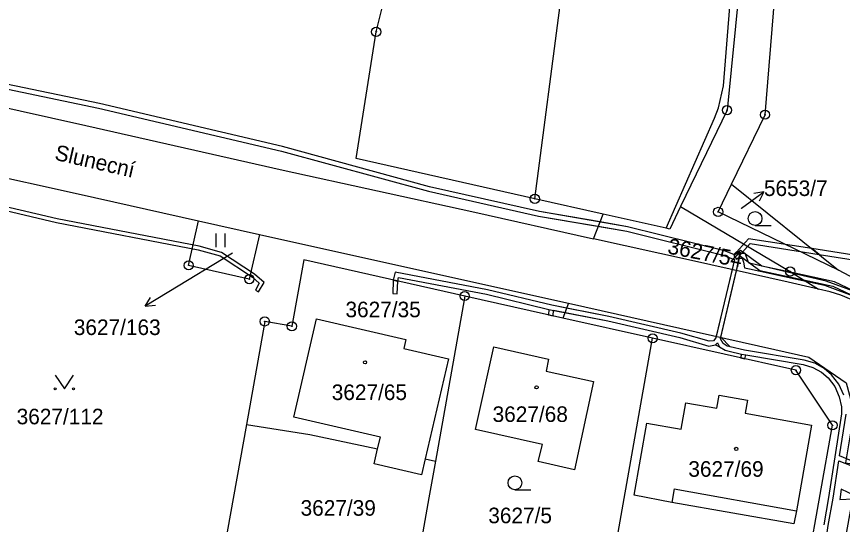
# Model space of a CAD drawing. Extents: x -644096 to -634268, y -1141430 to -1133463.
# Drawn here: x -640663.3 to -640573.2, y -1137723.5 to -1137668.1 of the extents above; entities that cross this region are included whole.
import ezdxf

# ---------------------------------------------------------------- set-up
doc = ezdxf.new("R2010")
doc.units = 0
for name, color, linetype in [('_CIVIL_CONSTRUCTION', 7, 'Continuous'), ('B_Hranice _3D', 7, 'Continuous'), ('M_Svah_Nasyp', 7, 'Continuous'), ('M_Svah_Zarez', 7, 'Continuous'), ('svrsek_osa_sjezdy', 7, 'Continuous'), ('svrsek_osa_VRT', 7, 'Continuous'), ('svrsek_popisy_VRT', 7, 'Continuous'), ('terminal_VRT', 7, 'Continuous')]:
    doc.layers.add(name, color=color, linetype=linetype)

msp = doc.modelspace()

# ---------------------------------------------------------------- linework, layer by layer
at = {"layer": '_CIVIL_CONSTRUCTION'}
for centre, radius in [((-640624.08, -1137669.79), 0.5), ((-640624.08, -1137669.79), 0.0303), ((-640585.78, -1137678.34), 0.5), ((-640585.78, -1137678.34), 0.0303), ((-640581.63, -1137678.84), 0.5), ((-640581.63, -1137678.84), 0.0303), ((-640606.76, -1137688.01), 0.5), ((-640606.76, -1137688.01), 0.0303), ((-640586.75, -1137689.44), 0.5), ((-640586.75, -1137689.44), 0.0303), ((-640644.55, -1137695.27), 0.5), ((-640644.55, -1137695.27), 0.0303), ((-640578.89, -1137695.94), 0.5), ((-640637.93, -1137696.78), 0.5), ((-640578.89, -1137695.94), 0.0303), ((-640637.93, -1137696.78), 0.0303), ((-640614.41, -1137698.62), 0.5), ((-640614.41, -1137698.62), 0.0303), ((-640636.24, -1137701.39), 0.5), ((-640636.24, -1137701.39), 0.0303), ((-640633.28, -1137701.92), 0.5), ((-640633.28, -1137701.92), 0.0303), ((-640593.9, -1137703.23), 0.5), ((-640593.9, -1137703.23), 0.0303), ((-640578.26, -1137706.71), 0.5), ((-640578.26, -1137706.71), 0.0303), ((-640574.26, -1137712.72), 0.5), ((-640574.26, -1137712.72), 0.0303)]:
    msp.add_circle(centre, radius, dxfattribs=at)
at = {"layer": 'B_Hranice _3D'}
for points in [[(-640549.77, -1137578.81), (-640550.43, -1137582.83), (-640551.07, -1137598.09), (-640551.86, -1137613.51), (-640556.82, -1137647.62), (-640558.57, -1137666.41), (-640560, -1137686.48), (-640560.91, -1137694.7), (-640563.67, -1137695.47), (-640576.51, -1137693.45), (-640575.72, -1137694.09), (-640563.65, -1137695.99), (-640560.45, -1137695.1), (-640559.5, -1137686.52), (-640558.07, -1137666.45), (-640556.32, -1137647.68), (-640551.36, -1137613.55), (-640550.57, -1137598.11), (-640549.93, -1137582.89), (-640549.27, -1137578.87), (-640548.65, -1137573.37), (-640549.08, -1137572.82)], [(-640583.45, -1137692.36), (-640584.76, -1137693.83), (-640584.38, -1137694.17), (-640583.25, -1137692.9), (-640575.72, -1137694.09), (-640576.51, -1137693.45)], [(-640562.15, -1137701.9), (-640563.49, -1137703.46), (-640564.2, -1137703.86), (-640565.14, -1137703.38), (-640567.68, -1137700.83), (-640570.04, -1137698.97), (-640574.05, -1137697.06), (-640578.7, -1137696.06), (-640581.98, -1137695.35), (-640584.32, -1137693.66), (-640585.05, -1137694.18), (-640584.76, -1137694.59), (-640584.32, -1137694.28), (-640582.19, -1137695.82), (-640577.42, -1137696.85), (-640574.21, -1137697.54), (-640570.3, -1137699.39), (-640568.02, -1137701.21), (-640565.44, -1137703.78), (-640564.18, -1137704.42), (-640563.15, -1137703.84), (-640561.7, -1137702.13)], [(-640538.26, -1137717), (-640539.71, -1137717.66), (-640559.3, -1137716.67), (-640560.67, -1137716.88), (-640562.49, -1137718.19), (-640563.8, -1137720.76), (-640564.48, -1137721.49), (-640565.79, -1137721.76), (-640571.78, -1137720.4), (-640573.31, -1137719.7), (-640573.48, -1137720.81), (-640572.04, -1137720.75), (-640565.8, -1137722.19), (-640564.28, -1137721.85), (-640563.47, -1137721), (-640562.18, -1137718.46), (-640560.51, -1137717.26), (-640559.28, -1137717.07), (-640541.12, -1137717.99), (-640538.13, -1137718.42), (-640537.86, -1137718.44), (-640537.1, -1137717.5)]]:
    msp.add_lwpolyline(points, close=True, dxfattribs=at)
for points in [[(-640570.99, -1137698.44), (-640574.97, -1137696.98), (-640578.55, -1137696.15), (-640583.18, -1137695.08), (-640583.41, -1137695.03), (-640583.8, -1137693.98), (-640584.54, -1137693.98), (-640585.02, -1137694.09), (-640586.04, -1137693.67), (-640596.63, -1137691.06), (-640599.64, -1137690.54), (-640606.25, -1137689.4), (-640618.24, -1137686.69), (-640634.31, -1137682.32), (-640654.28, -1137677.63), (-640676.38, -1137673.04)], [(-640585.44, -1137704.15), (-640585.77, -1137704.07), (-640586.21, -1137703.79), (-640586.49, -1137703.27), (-640584.32, -1137694.03), (-640584.78, -1137693.84), (-640585.02, -1137694.09), (-640586.04, -1137693.67), (-640596.63, -1137691.06), (-640606.25, -1137689.4), (-640618.24, -1137686.69), (-640634.31, -1137682.32), (-640654.28, -1137677.63), (-640676.38, -1137673.04)], [(-640676.48, -1137673.52), (-640654.38, -1137678.11), (-640634.43, -1137682.8), (-640618.36, -1137687.17), (-640606.35, -1137689.9), (-640599.83, -1137691.01), (-640596.73, -1137691.54), (-640586.2, -1137694.15), (-640585.18, -1137694.57), (-640584.97, -1137694.62), (-640585.23, -1137695.74), (-640586.95, -1137703.01), (-640586.99, -1137703.19), (-640587.27, -1137703.49), (-640587.74, -1137703.55), (-640590.81, -1137702.68), (-640598.68, -1137700.84), (-640603.29, -1137699.95), (-640604.92, -1137699.63), (-640611.92, -1137697.95), (-640622.01, -1137696.03), (-640622.21, -1137696.87), (-640621.72, -1137696.98), (-640621.63, -1137696.61), (-640612.02, -1137698.43), (-640605.23, -1137700.07), (-640598.78, -1137701.32), (-640590.93, -1137703.16), (-640587.78, -1137704.07), (-640587.03, -1137703.95), (-640586.59, -1137704.15), (-640585.97, -1137704.53)], [(-640676.48, -1137673.52), (-640654.38, -1137678.11), (-640634.43, -1137682.8), (-640618.36, -1137687.17), (-640606.35, -1137689.9), (-640596.73, -1137691.54), (-640586.2, -1137694.15), (-640585.18, -1137694.57), (-640584.97, -1137694.62), (-640586.99, -1137703.19), (-640587.27, -1137703.49), (-640587.74, -1137703.55), (-640590.81, -1137702.68), (-640598.68, -1137700.84), (-640604.92, -1137699.63), (-640611.92, -1137697.95), (-640622.01, -1137696.03), (-640622.21, -1137696.87), (-640622.22, -1137696.92), (-640622.27, -1137698.35), (-640621.77, -1137698.37), (-640621.72, -1137696.98), (-640621.63, -1137696.61), (-640612.02, -1137698.43), (-640605.23, -1137700.07), (-640605.26, -1137700.68), (-640604.76, -1137700.79), (-640604.73, -1137700.17), (-640598.78, -1137701.32), (-640590.93, -1137703.16), (-640587.78, -1137704.07), (-640587.03, -1137703.95), (-640586.82, -1137703.73), (-640586.59, -1137704.15), (-640585.97, -1137704.53), (-640585.56, -1137704.63), (-640584.21, -1137704.95), (-640584.31, -1137705.36), (-640583.82, -1137705.47), (-640583.72, -1137705.05), (-640577.46, -1137706.1), (-640576.41, -1137706.41), (-640575.46, -1137706.93), (-640574.73, -1137707.54), (-640574.01, -1137708.5), (-640573.52, -1137709.6), (-640573.29, -1137710.71), (-640573.27, -1137711.48), (-640574.02, -1137716.15), (-640574.7, -1137720.58), (-640575.22, -1137723.57)], [(-640673.47, -1137687.19), (-640658.97, -1137690.58), (-640643.51, -1137693.57), (-640641.11, -1137694.24), (-640637.59, -1137696.55), (-640636.84, -1137697.22), (-640637.27, -1137697.96), (-640636.93, -1137698.16), (-640636.32, -1137697.14), (-640637.35, -1137696.23), (-640640.95, -1137693.88), (-640643.41, -1137693.19), (-640658.89, -1137690.18), (-640673.37, -1137686.81)], [(-640573.04, -1137709.44), (-640573.57, -1137708.24), (-640574.37, -1137707.2), (-640575.18, -1137706.51), (-640576.21, -1137705.95), (-640577.34, -1137705.62), (-640583.86, -1137704.51), (-640585.44, -1137704.15), (-640586.46, -1137703.12), (-640584.75, -1137695.84), (-640584.43, -1137694.48), (-640584.14, -1137694.48), (-640583.97, -1137694.94), (-640583.88, -1137695.53), (-640583.32, -1137695.65), (-640577.18, -1137696.99), (-640575.15, -1137697.44), (-640571.23, -1137698.88)], [(-640585.97, -1137704.53), (-640585.56, -1137704.63), (-640584.21, -1137704.95), (-640583.72, -1137705.05), (-640577.46, -1137706.1), (-640576.41, -1137706.41), (-640575.46, -1137706.93), (-640574.73, -1137707.54), (-640574.01, -1137708.5), (-640573.52, -1137709.6), (-640573.29, -1137710.71), (-640573.27, -1137711.48), (-640574.02, -1137716.15), (-640574.7, -1137720.58), (-640575.22, -1137723.57)], [(-640573.04, -1137709.44), (-640573.57, -1137708.24), (-640574.37, -1137707.2), (-640575.18, -1137706.51), (-640576.21, -1137705.95), (-640577.34, -1137705.62), (-640583.86, -1137704.51), (-640585.44, -1137704.15)], [(-640571.93, -1137716.69), (-640573.5, -1137716.07), (-640572.77, -1137711.52)], [(-640571.93, -1137716.69), (-640573.5, -1137716.07), (-640572.77, -1137711.52)], [(-640580.04, -1137765.13), (-640581.99, -1137764.78), (-640581.7, -1137761.53), (-640579.9, -1137751.21), (-640577.41, -1137739.24), (-640575.24, -1137727.16), (-640574.72, -1137723.65), (-640574.2, -1137720.66), (-640573.58, -1137716.61), (-640572.07, -1137717.17)], [(-640572.58, -1137767.09), (-640573.23, -1137766.37), (-640581.99, -1137764.78), (-640581.7, -1137761.53), (-640579.9, -1137751.21), (-640577.41, -1137739.24), (-640575.24, -1137727.16), (-640574.72, -1137723.65), (-640574.2, -1137720.66), (-640573.58, -1137716.61), (-640572.07, -1137717.17)]]:
    msp.add_lwpolyline(points, dxfattribs=at)
at = {"layer": 'M_Svah_Nasyp'}
for q in [(-640591.81, -1137721.15), (-640578.2, -1137722.04)]:
    msp.add_line((-640591.55, -1137719.67), q, dxfattribs=at)
at = {"layer": 'M_Svah_Zarez'}
for centre in [(-640625.297, -1137705.849), (-640606.567, -1137708.579), (-640584.777, -1137715.299)]:
    msp.add_circle(centre, 0.175, dxfattribs=at)
at = {"layer": 'svrsek_osa_sjezdy'}
for p, q in [((-640582.713, -1137690.91), (-640580.963, -1137690.91)), ((-640641.561, -1137693.29), (-640641.561, -1137691.79)), ((-640640.56, -1137693.29), (-640640.56, -1137691.79)), ((-640608.933, -1137719.75), (-640607.183, -1137719.75))]:
    msp.add_line(p, q, dxfattribs=at)
msp.add_lwpolyline([(-640659.12, -1137707.249), (-640658.12, -1137708.75), (-640657.12, -1137707.249)], dxfattribs=at)
for centre, radius in [((-640582.713, -1137690.16), 0.75), ((-640659.12, -1137708.749), 0.1), ((-640657.12, -1137708.749), 0.1), ((-640608.933, -1137719), 0.75)]:
    msp.add_circle(centre, radius, dxfattribs=at)
at = {"layer": 'svrsek_popisy_VRT'}
for p, q in [((-640584.19, -1137689.03), (-640581.762, -1137687.266)), ((-640581.762, -1137687.266), (-640582.867, -1137687.45)), ((-640581.762, -1137687.266), (-640582.278, -1137688.26)), ((-640584.25, -1137689.08), (-640584.19, -1137689.03)), ((-640639.75, -1137693.93), (-640646.73, -1137698.17)), ((-640646.73, -1137698.17), (-640649.302, -1137699.716)), ((-640649.302, -1137699.716), (-640648.702, -1137698.771)), ((-640649.302, -1137699.716), (-640648.186, -1137699.629))]:
    msp.add_line(p, q, dxfattribs=at)
at = {"layer": 'terminal_VRT'}
for p, q in [((-640606.76, -1137688.01), (-640601.05, -1137644.12)), ((-640585.28, -1137686.4), (-640573.6, -1137695.79)), ((-640599.31, -1137689.68), (-640606.76, -1137688.01)), ((-640600.35, -1137692.36), (-640599.31, -1137689.68)), ((-640592.43, -1137691.22), (-640599.31, -1137689.68)), ((-640643.46, -1137690.41), (-640636.81, -1137691.89)), ((-640559.98, -1137703.05), (-640573.6, -1137695.79)), ((-640574.51, -1137698.15), (-640575.78, -1137697.86)), ((-640614.41, -1137698.62), (-640617.62, -1137716.62)), ((-640603.71, -1137701.03), (-640614.41, -1137698.62)), ((-640603.08, -1137699.4), (-640603.71, -1137701.03)), ((-640593.9, -1137703.23), (-640603.71, -1137701.03)), ((-640598.98, -1137731.72), (-640593.9, -1137703.23)), ((-640638.24, -1137712.65), (-640640.33, -1137724.36)), ((-640618.73, -1137716.39), (-640617.62, -1137716.62))]:
    msp.add_line(p, q, dxfattribs=at)
for points in [[(-640606.76, -1137688.01), (-640626.26, -1137683.62), (-640624.08, -1137669.79), (-640623.24, -1137666.46), (-640618.05, -1137632.56)], [(-640585.28, -1137686.4), (-640581.63, -1137678.84), (-640578.31, -1137638.29)], [(-640592.43, -1137691.22), (-640587.15, -1137679.22), (-640586.7, -1137678.1), (-640586.16, -1137675.69), (-640583.83, -1137646.6)], [(-640582.64, -1137646.77), (-640585.78, -1137678.34), (-640590.85, -1137688.84)], [(-640700.85, -1137670.04), (-640677.31, -1137675.23), (-640655.78, -1137680.03), (-640634.24, -1137684.87), (-640613.63, -1137689.4), (-640600.35, -1137692.36)], [(-640681.01, -1137698.34), (-640680.73, -1137697), (-640681.97, -1137696.71), (-640686.58, -1137686.07), (-640668.96, -1137689.93), (-640667.8, -1137684.98), (-640656.6, -1137687.48), (-640643.46, -1137690.41)], [(-640573.6, -1137695.79), (-640586.75, -1137689.44), (-640585.28, -1137686.4)], [(-640590.85, -1137688.84), (-640592.04, -1137691.31), (-640592.43, -1137691.22)], [(-640590.85, -1137688.84), (-640578.89, -1137695.94), (-640575.78, -1137697.86)], [(-640636.81, -1137691.89), (-640637.93, -1137696.78), (-640644.55, -1137695.27), (-640643.46, -1137690.41)], [(-640636.81, -1137691.89), (-640614.74, -1137696.81), (-640603.08, -1137699.4)], [(-640575.78, -1137697.86), (-640579.12, -1137697.11), (-640589.66, -1137694.74), (-640600.35, -1137692.36)], [(-640614.41, -1137698.62), (-640631.99, -1137694.67), (-640633.28, -1137701.92), (-640636.24, -1137701.39), (-640638.24, -1137712.65)], [(-640566.69, -1137703.44), (-640567.481, -1137702.499), (-640568.346, -1137701.625), (-640569.28, -1137700.825), (-640570.079, -1137700.236), (-640571.119, -1137699.581), (-640572.209, -1137699.012), (-640573.342, -1137698.535), (-640574.51, -1137698.15)], [(-640603.08, -1137699.4), (-640580.57, -1137704.44), (-640576.84, -1137705.28), (-640572.78, -1137708.1), (-640571.95, -1137711.19), (-640572.1, -1137712.44), (-640572.85, -1137716.82), (-640571.44, -1137717.02), (-640576.03, -1137742.71), (-640580.37, -1137766.99), (-640581.09, -1137768.77), (-640583.2, -1137771.18), (-640589.04, -1137772.57), (-640591.83, -1137772.06)], [(-640623.92, -1137715.3), (-640623.62, -1137714.01), (-640633.07, -1137711.82), (-640630.59, -1137701.1), (-640620.84, -1137703.36), (-640621.06, -1137704.34), (-640616.19, -1137705.46), (-640618.73, -1137716.39)], [(-640578.3, -1137735.41), (-640574.26, -1137712.72), (-640578.26, -1137706.71), (-640593.9, -1137703.23)], [(-640605.52, -1137706.8), (-640600.34, -1137707.93), (-640602.44, -1137717.59), (-640606.38, -1137716.66), (-640605.94, -1137714.83), (-640613.23, -1137713.18), (-640611.25, -1137704.16), (-640605.28, -1137705.49), (-640605.52, -1137706.8)], [(-640583.55, -1137709.99), (-640583.81, -1137711.4), (-640576.57, -1137712.71), (-640578.2, -1137722.04), (-640578.47, -1137723.46), (-640591.81, -1137721.15), (-640595.93, -1137720.36), (-640594.53, -1137712.48), (-640590.78, -1137713.16), (-640590.26, -1137710.27), (-640586.89, -1137710.85), (-640586.62, -1137709.45), (-640583.55, -1137709.99)], [(-640638.24, -1137712.65), (-640631.32, -1137713.74), (-640623.92, -1137715.3)], [(-640618.73, -1137716.39), (-640619.13, -1137718.13), (-640624.29, -1137716.93), (-640623.92, -1137715.3)], [(-640617.62, -1137716.62), (-640618.33, -1137720.65), (-640619.65, -1137728.04)]]:
    msp.add_lwpolyline(points, dxfattribs=at)

# ---------------------------------------------------------------- texts
at = {"layer": 'svrsek_osa_VRT'}
for s, p in [('5653/7', (-640581.75, -1137687.705)), ('3627/35', (-640627.43, -1137700.935)), ('3627/163', (-640657.087, -1137702.872)), ('3627/65', (-640628.93, -1137709.965)), ('3627/112', (-640663.327, -1137712.612)), ('3627/68', (-640611.37, -1137712.355)), ('3627/69', (-640590, -1137718.335)), ('3627/39', (-640632.33, -1137722.585)), ('3627/5', (-640611.84, -1137723.405))]:
    msp.add_text(s, height=1.7, dxfattribs=at).set_placement(p)
msp.add_text('3627/54', height=1.7, rotation=349, dxfattribs=at).set_placement((-640592.352, -1137693.965))
at = {"layer": 'svrsek_popisy_VRT'}
msp.add_text('Slunecní', height=1.7, rotation=347, dxfattribs=at).set_placement((-640659.274, -1137683.733))

doc.saveas('drawing.dxf')
